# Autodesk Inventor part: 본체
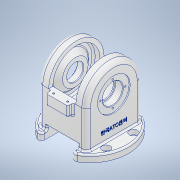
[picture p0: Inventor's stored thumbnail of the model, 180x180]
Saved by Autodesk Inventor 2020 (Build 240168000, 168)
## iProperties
Created: 2024-08
Part Number: 본체
Material: 알루미늄 6061
Document SubType Name: Modeling
Designer: oem
Density: 2.7 g/cm^3
Appearance: 알루미늄 - 평지
Mass: 1450.44 g
Surface Area: 999.401 cm^2
Volume: 537.201 cm^3
Author: oem
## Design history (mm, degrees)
sketch "스케치1"
  geometry: L1 (-81, -51)-(0, -51); L2 (-81, -51)-(-81, 51); L3 (0, 51)-(-81, 51); A1 r 51 centre (0, 0) between (0, -51) and (0, 51); 2 further points
  constraints: 6 end point, 2 point on circle, 2 tangent, 1 centre point, 1 coincident, 1 horizontal, 1 horizontal alignment, 1 midpoint, 1 parallel, 1 vertical
  dimensions: "d7" = 102 diameter of A1; "d8" = 81 distance from line of point (0, 0) L2
extrude "돌출1" new body sketch "스케치1" stored distance "d3" = 88; taper "d4" = 0 deg
sketch "스케치3"
  geometry: L1 (0, 81)-(88, 81) reference; L2 (0, 132)-(88, 132) reference; L3 (44, 132)-(44, 0); L4 (0, 0)-(88, 0) reference; L5 (0, 81)-(88, 81) reference; L6 (19, 132)-(69, 132); L7 (69, 132)-(69, 81); L8 (69, 81)-(19, 81); L9 (19, 81)-(19, 132); 7 further points
  constraints: 10 end point, 5 midpoint, 2 parallel, 1 coincident, 1 horizontal, 1 perpendicular, 1 point on line
  dimensions: "d9" = 50 distance between parallel lines of L9 L7
extrude "돌출2" cut sketch "스케치3" extent not by distance; stored distance "d10" = 88; taper "d11" = 0 deg
sketch "스케치4"
  geometry: C1 r 71 at (44, 51); 1 further point
  constraints: 1 centre point, 1 coincident
  dimensions: "d12" = 142 diameter of C1
extrude "돌출3" join sketch "스케치4" distance "d13" = 13; taper "d14" = 0 deg
sketch "스케치5"
  geometry: L1 (0, 0)-(50, 0) reference; L2 (0, 102)-(50, 102) reference; L3 (0, 0)-(0, 102) reference; L4 (0, 0)-(50, 0) reference; L5 (50, 0)-(50, 102) reference; L6 (5, 102)-(45, 102); L7 (45, 102)-(45, 112); L8 (45, 112)-(5, 112); L9 (5, 112)-(5, 102); L10 (-27.085, 51)-(83.028, 51); L11 (0, 0)-(50, 0); L12 (0, 0)-(50, 0); L13 (5, 0)-(45, 0); L14 (45, 0)-(45, -10); L15 (45, -10)-(5, -10); L16 (5, -10)-(5, 0); 7 further points
  constraints: 22 end point, 9 symmetric about line, 3 midpoint, 2 horizontal, 2 parallel, 2 point on line, 1 coincident, 1 perpendicular, 1 vertical alignment
  dimensions: "d15" = 40 distance of L7.end L8.end; "d16" = 122 distance between parallel lines of L15 L8
extrude "돌출4" join sketch "스케치5" distance "d17" = 20; taper "d18" = 0 deg
sketch "스케치8"
  geometry: L1 (50, 0)-(50, 102) reference; L2 (-19, 51)-(69, 51); L3 (-19, 102)-(-19, 0) reference; L4 (52, 27.5)-(62, 17.5); L5 (62, 17.5)-(62, 10.5); L6 (59, 7.5)-(25, 7.5); L7 (25, 7.5)-(25, 51); L8 (-2, 27.5)-(-12, 17.5); L9 (-12, 17.5)-(-12, 10.5); L10 (-9, 7.5)-(25, 7.5); L11 (-2, 27.5)-(-2, 51); L12 (52, 27.5)-(52, 51); A1 r 3 centre (-9, 10.5) between (-12, 10.5) and (-9, 7.5); A2 r 3 centre (59, 10.5) between (59, 7.5) and (62, 10.5); 6 further points
  constraints: 20 end point, 10 point on line, 4 point on circle, 4 tangent, 3 midpoint, 3 perpendicular, 3 symmetric about line, 2 centre point, 2 coincident, 1 equal radius, 1 horizontal, 1 horizontal alignment, 1 vertical
  dimensions: "d33" = 45 deg angle of L6 L4; "d34" = 67 diameter of L4.end L2; "d36" = 12 distance between parallel lines of L1 L5; "d37" = 3 radius of A1; "d118" = 87 diameter of L6 L2; "d131" = 54 distance between parallel lines of L12 L11
revolve "회전1" sketch "스케치8" stored, may be unused: angle "d38" = 90 deg
sketch "스케치9"
  geometry: C1 r 16 at (0, 0); C2 r 18.5 at (0, 0); C3 r 30 at (0, 0); A1 r 51 centre (0, 0) between (51, 0) and (-51, 0) reference
  constraints: 3 centre point, 3 coincident
  dimensions: "d39" = 32 diameter of C1; "d40" = 37 diameter of C2; "d41" = 60 diameter of C3
extrude "돌출5" cut sketch "스케치9" extent not by distance; stored distance "d42" = 0; taper "d43" = 0 deg
extrude "돌출6" cut sketch "스케치9" distance "d44" = 15; taper "d45" = 0 deg
extrude "돌출7" cut sketch "스케치9" distance "d46" = 2; taper "d47" = 0 deg
sketch "스케치10"
  geometry: L1 (-55, 25)-(55, 25); L2 (55, 25)-(55, -25); C1 r 71 at (0, 0) reference; 3 further points
  constraints: 4 end point, 2 horizontal alignment, 2 midpoint, 2 vertical alignment, 1 horizontal, 1 vertical
  dimensions: "d48" = 110 distance of L1.start L1.end; "d49" = 50 distance of L2.end L1.end
hole "구멍1" sketch "스케치10" at (-55, 25), (55, 25), (55, -25), (-55, -25) diameter "d50" = 9; stored, may be unused: countersink angle "d54" = 90 deg, drill point angle "d56" = 118 deg; dims "d51" = 6, "d52" = 15, "d53" = 8.8, "d55" = 8
sketch "스케치11"
  geometry: 2 further points
  constraints: 1 vertical alignment
  dimensions: "d64" = 23 distance of point (0, 0) point (0, 23)
hole "구멍2" sketch "스케치11" at (0, 23) diameter "d57" = 3.242; stored, may be unused: countersink angle "d61" = 90 deg, drill point angle "d63" = 118 deg; dims "d58" = 8, "d59" = 15, "d60" = 8.8, "d62" = 10
sketch "스케치12"
  geometry: L1 (72, -81)-(72, -62); L2 (72, -62)-(16, -62); L3 (16, -62)-(16, -81); L4 (-27, -81)-(115, -81) reference; L5 (72, -81)-(16, -81); 4 further points
  constraints: 8 end point, 3 midpoint, 2 coincident, 1 parallel, 1 perpendicular, 1 vertical alignment
  dimensions: "d68" = 56 distance of L1.end L2.end; "d93" = 19 distance from line of L1.start L2; "d94" = 28 horizontal distance of L3.end point (44, 0)
extrude "돌출8" cut sketch "스케치12" extent not by distance; stored distance "d70" = 14.246; taper "d71" = 0 deg
sketch "스케치13"
  geometry: C1 r 11 at (28, -51); 1 further point
  constraints: 1 centre point, 1 coincident
  dimensions: "d72" = 22 diameter of C1
extrude "돌출9" cut sketch "스케치13" extent not by distance; stored distance "d73" = 15; taper "d74" = 0 deg
chamfer "모따기1" distance "d78" = 1; stored, may be unused: second distance "d79" = 2, angle "d80" = 45 deg
sketch "스케치17"
  geometry: L1 (-65.246, -81)-(65.246, -81) reference; 2 further points
  constraints: 1 midpoint, 1 vertical alignment, 1 other
  dimensions: "d95" = 30 distance from line of L1 point (0, -51)
feature "엠보싱1" sketch "스케치17" dims "d9" = 50, "d96" = 0.5, "d97" = 0
sketch "스케치18"
  geometry: L1 (0, 112)-(40, 112) reference; L2 (7, 115)-(33, 115); L3 (33, 115)-(33, 7); 4 further points
  constraints: 4 end point, 3 horizontal alignment, 3 vertical alignment, 2 midpoint, 1 horizontal, 1 perpendicular
  dimensions: "d98" = 26 distance of L2.end L2.start; "d99" = 108 distance of point (7, 7) L2.start
hole "구멍4" sketch "스케치18" at (7, 7), (33, 7), (7, 115), (33, 115) diameter "d100" = 3.242; stored, may be unused: countersink angle "d104" = 90 deg, drill point angle "d106" = 118 deg; dims "d101" = 8, "d102" = 15, "d103" = 8.8, "d105" = 10
fillet "모깎기1" dims "d107" = 3
sketch "스케치20"
  geometry: C1 r 11 at (0, 0) reference; C2 r 30 at (0, 0)
  constraints: 1 centre point, 1 coincident
  dimensions: "d112" = 60 diameter of C2
extrude "돌출12" cut sketch "스케치20" distance "d113" = 22; taper "d114" = 0 deg
sketch "스케치21"
  geometry: C1 r 14 at (0, 0); A1 r 71 centre (0, 0) between (28, -65.246) and (28, 65.246) reference
  constraints: 1 centre point, 1 coincident
  dimensions: "d115" = 28 diameter of C1
extrude "돌출13" cut sketch "스케치21" distance "d116" = 37; taper "d117" = 0 deg
fillet "모깎기3" dims "d119" = 8
fillet "모깎기4" dims "d120" = 3
fillet "모깎기5" dims "d121" = 3
fillet "모깎기6" dims "d122" = 3
fillet "모깎기7" dims "d123" = 3
fillet "모깎기10" dims "d126" = 6
fillet "모깎기11" dims "d127" = 3
node "솔리드1"
mirror "미러1"
pattern_circular "원형 패턴1" dims angle "d66" = 360 deg
mirror "미러2"
node "투영된 루프1"
feature "A9D066F2-1C7D-4E18-AEED-F7BC21143FA4" dims "d50" = 9, "d51" = 6, "d52" = 15, "d53" = 8.8, "d54" = 90 deg, "d55" = 8, "d56" = 118 deg
